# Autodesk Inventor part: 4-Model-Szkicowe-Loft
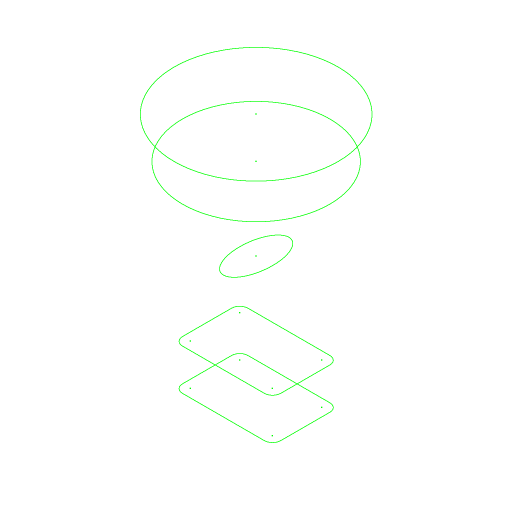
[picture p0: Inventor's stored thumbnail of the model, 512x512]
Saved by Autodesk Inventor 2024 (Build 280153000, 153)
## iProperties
Company: ATC
Shininess: 20.0
Length Units: 11269
Angle Units: 11279
Time Units: 11290
Mass Units: 11283
Length Display Precision: 3
Angle Display Precision: 2
Compacted: True
Created: 2023-03
Part Number: 4-Model-Szkicowe-Loft
Document SubType Name: Modeling
Designer: Andrzej Jaskulski
Material: Kurs-AJ
Density: 1 g/cm^3
Appearance: Kurs-AJ
Checked By: A.J.
Engr Approved By: Andrzej Jaskulski
Mfg Approved By: Andrzej Jaskulski
Authority: A.J.
Density: 0.0
Volumn: 0.0
Area: 0.0
PropertySet Name: Model Information
Control State: 0
Master: False
Checked Out: False
Title: A.J.: Kurs R2024-MEP
Author: Andrzej Jaskulski
Revision Number: 1/24
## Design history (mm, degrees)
workplane "Work Plane1"
workplane "Work Plane3"
workplane "Work Plane4"
workplane "Work Plane5"
sketch "Sketch 1"
  geometry: L1 (-5, -4)-(5, -4); L2 (6, -3)-(6, 3); L3 (5, 4)-(-5, 4); L4 (-6, 3)-(-6, -3); A1 r 1 centre (5, 3) between (6, 3) and (5, 4); A2 r 1 centre (5, -3) between (5, -4) and (6, -3); A3 r 1 centre (-5, -3) between (-6, -3) and (-5, -4); A4 r 1 centre (-5, 3) between (-5, 4) and (-6, 3)
  constraints: 8 end point, 8 point on circle, 8 tangent, 4 centre point, 3 equal radius, 2 parallel, 1 horizontal, 1 perpendicular
sketch "Sketch 2"
  geometry: L1 (-5, -4)-(5, -4); L2 (6, -3)-(6, 3); L3 (5, 4)-(-5, 4); L4 (-6, 3)-(-6, -3); A1 r 1 centre (5, 3) between (6, 3) and (5, 4); A2 r 1 centre (5, -3) between (5, -4) and (6, -3); A3 r 1 centre (-5, -3) between (-6, -3) and (-5, -4); A4 r 1 centre (-5, 3) between (-5, 4) and (-6, 3)
  constraints: 8 end point, 8 point on circle, 8 tangent, 4 centre point, 3 equal radius, 2 parallel, 1 horizontal, 1 perpendicular
sketch "Sketch 3"
  geometry: 1 further point; 1 other entity
  constraints: 2 other
sketch "Sketch 4"
  geometry: C1 r 9 at (0, 0)
  constraints: 1 centre point
sketch "Sketch 5"
  geometry: C1 r 10 at (0, 0)
  constraints: 1 centre point
node "Korpusy bryłowe"
node "Korpusy powierzchniowe"
other parameters: "d2" = -5, "d5" = 5
